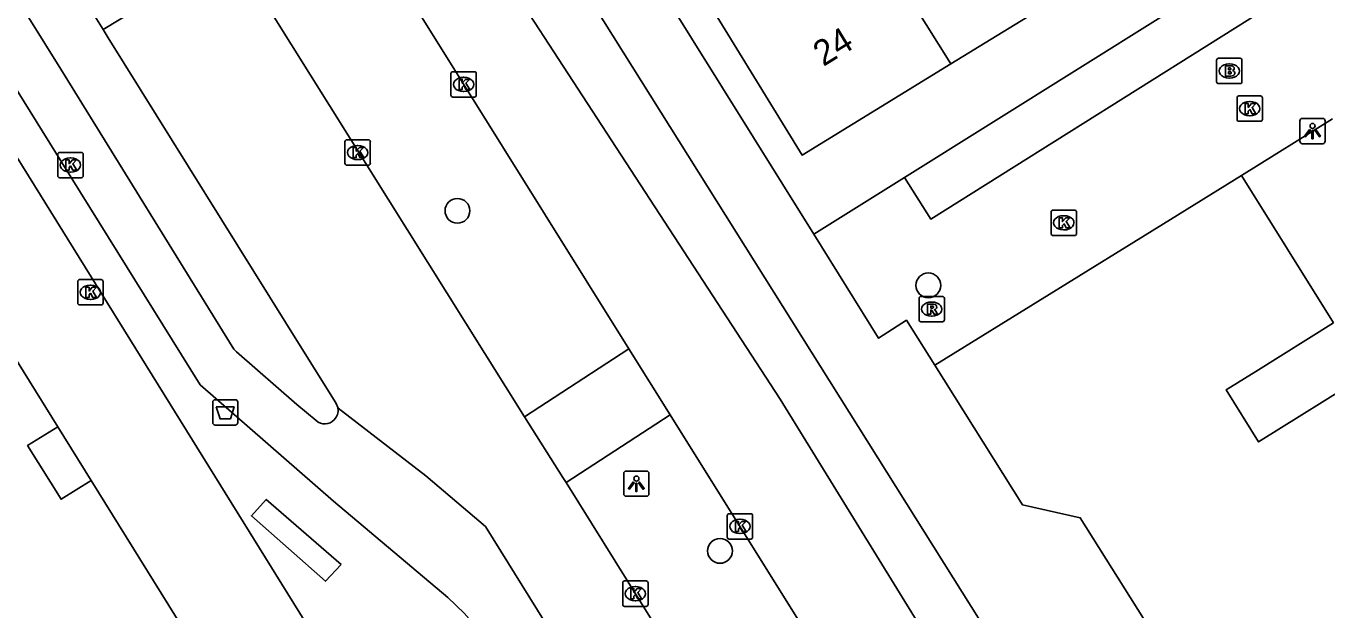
# Model space of a CAD drawing. Extents: x 158461 to 159795, y 387220 to 388672.
# Drawn here: x 158762.6 to 158813.9, y 388009.1 to 388032.1 of the extents above; entities that cross this region are included whole.
import ezdxf

# ---------------------------------------------------------------- set-up
doc = ezdxf.new("R2010")
doc.units = 0
for name, color, linetype in [('IMGEO_Afvalbak', 7, 'Continuous'), ('IMGEO_Boom', 7, 'Continuous'), ('IMGEO_Brandkraan', 7, 'Continuous'), ('IMGEO_Kolk', 7, 'Continuous'), ('IMGEO_Lichtpunt', 7, 'Continuous'), ('IMGEO_Muur', 7, 'Continuous'), ('IMGEO_Pand', 7, 'Continuous'), ('IMGEO_Pand_nummerreeks', 7, 'Continuous'), ('IMGEO_Pand_overbouw', 7, 'Continuous'), ('IMGEO_Parkeervlak_open', 7, 'Continuous'), ('IMGEO_Rijbaan_lokaal_gesloten', 7, 'Continuous'), ('IMGEO_Rijbaan_lokaal_open', 7, 'Continuous'), ('IMGEO_Rioolput', 7, 'Continuous'), ('IMGEO_Voetpad_open', 7, 'Continuous')]:
    doc.layers.add(name, color=color, linetype=linetype)

msp = doc.modelspace()

# ---------------------------------------------------------------- linework, layer by layer
at = {"layer": 'IMGEO_Afvalbak'}
for p, q in [((158769.925, 388016.491), (158769.925, 388017.291)), ((158769.925, 388017.291), (158769.925, 388016.491)), ((158770.025, 388017.391), (158770.815, 388017.391)), ((158770.815, 388017.391), (158770.025, 388017.391)), ((158770.915, 388017.291), (158770.915, 388016.491)), ((158770.915, 388016.491), (158770.915, 388017.291)), ((158770.815, 388016.391), (158770.025, 388016.391)), ((158770.025, 388016.391), (158770.815, 388016.391))]:
    msp.add_line(p, q, dxfattribs=at)
msp.add_lwpolyline([(158770.068, 388017.105), (158770.772, 388017.105), (158770.623, 388016.635), (158770.217, 388016.635), (158770.068, 388017.105)], dxfattribs=at)
for centre, start, end in [((158770.025, 388017.291), 90, 180), ((158770.025, 388017.291), 90, 180), ((158770.815, 388017.291), 0, 90), ((158770.815, 388017.291), 360, 90), ((158770.025, 388016.491), 180, 270), ((158770.025, 388016.491), 180, 270), ((158770.815, 388016.491), 270, 0), ((158770.815, 388016.491), 270, 0)]:
    msp.add_arc(centre, 0.1, start, end, dxfattribs=at)
at = {"layer": 'IMGEO_Boom'}
for centre in [(158779.58, 388024.844), (158798.158, 388021.903), (158789.94, 388011.426)]:
    msp.add_circle(centre, 0.489, dxfattribs=at)
at = {"layer": 'IMGEO_Brandkraan'}
for p, q in [((158809.53, 388029.937), (158809.53, 388030.789)), ((158809.605, 388030.863), (158810.457, 388030.863)), ((158810.531, 388030.789), (158810.531, 388029.937)), ((158810.018, 388030.643), (158810.043, 388030.643)), ((158810.457, 388029.863), (158809.605, 388029.863)), ((158810.041, 388030.083), (158810.016, 388030.083))]:
    msp.add_line(p, q, dxfattribs=at)
for points in [[(158809.53, 388029.937), (158809.53, 388030.789)], [(158809.605, 388030.863), (158810.457, 388030.863)], [(158810.531, 388030.789), (158810.531, 388029.937)], [(158809.878, 388030.563), (158809.878, 388030.163), (158810.091, 388030.163)], [(158810.109, 388030.563), (158809.878, 388030.563)], [(158810.057, 388030.482), (158810.003, 388030.482), (158810.003, 388030.406)], [(158810.003, 388030.406), (158810.056, 388030.406)], [(158810.065, 388030.33), (158810.003, 388030.33), (158810.003, 388030.249)], [(158810.003, 388030.249), (158810.065, 388030.249)], [(158810.457, 388029.863), (158809.605, 388029.863)]]:
    msp.add_lwpolyline(points, dxfattribs=at)
for centre, radius, start, end in [((158809.607, 388030.787), 0.0765, 91.552, 178.448), ((158809.607, 388030.787), 0.0765, 91.552, 178.448), ((158810.455, 388030.787), 0.0765, 1.552, 88.448), ((158810.455, 388030.787), 0.0765, 1.552, 88.448), ((158810.058, 388030.444), 0.0379, 267.8285, 90.9355), ((158810.066, 388030.289), 0.0404, 269.8759, 90.5077), ((158810.113, 388030.418), 0.145, 59.4692, 91.5367), ((158810.138, 388030.465), 0.0922, 285.5137, 58.1501), ((158810.143, 388030.273), 0.105, 301.3115, 78.989), ((158809.607, 388029.939), 0.0765, 181.552, 268.448), ((158809.607, 388029.939), 0.0765, 181.552, 268.448), ((158810.097, 388030.414), 0.251, 268.6676, 293.5347), ((158810.455, 388029.939), 0.0765, 271.552, 358.448), ((158810.455, 388029.939), 0.0765, 271.552, 358.448)]:
    msp.add_arc(centre, radius, start, end, dxfattribs=at)
for centre, major_axis, ratio, start_param, end_param in [((158810.017, 388030.363), (-0.387, 0.002), 0.722429, 4.712389, 7.853982), ((158810.042, 388030.363), (-0.39, 0.002), 0.717154, 1.570796, 4.712389)]:
    msp.add_ellipse(centre, major_axis=major_axis, ratio=ratio, start_param=start_param, end_param=end_param, dxfattribs=at)
at = {"layer": 'IMGEO_Kolk'}
for p, q in [((158779.324, 388029.405), (158779.324, 388030.257)), ((158779.399, 388030.331), (158780.251, 388030.331)), ((158780.325, 388030.257), (158780.325, 388029.405)), ((158779.812, 388030.111), (158779.837, 388030.111)), ((158780.251, 388029.331), (158779.399, 388029.331)), ((158779.835, 388029.551), (158779.81, 388029.551)), ((158810.337, 388028.45), (158810.337, 388029.302)), ((158810.412, 388029.376), (158811.264, 388029.376)), ((158811.338, 388029.302), (158811.338, 388028.45)), ((158810.825, 388029.156), (158810.85, 388029.156)), ((158811.264, 388028.376), (158810.412, 388028.376)), ((158810.848, 388028.596), (158810.823, 388028.596)), ((158775.143, 388026.718), (158775.143, 388027.57)), ((158775.218, 388027.644), (158776.07, 388027.644)), ((158775.631, 388027.424), (158775.656, 388027.424)), ((158776.144, 388027.57), (158776.144, 388026.718)), ((158763.814, 388026.223), (158763.814, 388027.075)), ((158763.889, 388027.149), (158764.741, 388027.149)), ((158764.302, 388026.929), (158764.327, 388026.929)), ((158764.815, 388027.075), (158764.815, 388026.223)), ((158776.07, 388026.644), (158775.218, 388026.644)), ((158775.654, 388026.864), (158775.629, 388026.864)), ((158764.741, 388026.149), (158763.889, 388026.149)), ((158764.325, 388026.369), (158764.3, 388026.369)), ((158803.002, 388023.944), (158803.002, 388024.796)), ((158803.077, 388024.87), (158803.929, 388024.87)), ((158803.49, 388024.65), (158803.515, 388024.65)), ((158804.003, 388024.796), (158804.003, 388023.944)), ((158803.513, 388024.09), (158803.488, 388024.09)), ((158803.929, 388023.87), (158803.077, 388023.87)), ((158764.602, 388021.202), (158764.602, 388022.054)), ((158764.677, 388022.128), (158765.529, 388022.128)), ((158765.603, 388022.054), (158765.603, 388021.202)), ((158765.09, 388021.908), (158765.115, 388021.908)), ((158765.529, 388021.128), (158764.677, 388021.128)), ((158765.113, 388021.348), (158765.088, 388021.348)), ((158790.223, 388011.965), (158790.223, 388012.817)), ((158790.298, 388012.891), (158791.15, 388012.891)), ((158791.224, 388012.817), (158791.224, 388011.965)), ((158790.711, 388012.671), (158790.736, 388012.671)), ((158791.15, 388011.891), (158790.298, 388011.891)), ((158790.734, 388012.111), (158790.709, 388012.111)), ((158786.176, 388010.237), (158787.028, 388010.237)), ((158786.101, 388009.311), (158786.101, 388010.163)), ((158786.589, 388010.017), (158786.614, 388010.017)), ((158787.102, 388010.163), (158787.102, 388009.311)), ((158787.028, 388009.237), (158786.176, 388009.237)), ((158786.612, 388009.457), (158786.587, 388009.457))]:
    msp.add_line(p, q, dxfattribs=at)
for points in [[(158779.324, 388029.405), (158779.324, 388030.257)], [(158779.399, 388030.331), (158780.251, 388030.331)], [(158780.325, 388030.257), (158780.325, 388029.405)], [(158779.645, 388030.031), (158779.768, 388030.031), (158779.768, 388029.88), (158779.898, 388030.031), (158780.062, 388030.031), (158779.916, 388029.88), (158780.069, 388029.631), (158779.917, 388029.631), (158779.832, 388029.795), (158779.768, 388029.728), (158779.768, 388029.631), (158779.645, 388029.631), (158779.645, 388030.031)], [(158780.251, 388029.331), (158779.399, 388029.331)], [(158810.337, 388028.45), (158810.337, 388029.302)], [(158810.412, 388029.376), (158811.264, 388029.376)], [(158811.338, 388029.302), (158811.338, 388028.45)], [(158810.658, 388029.076), (158810.781, 388029.076), (158810.781, 388028.925), (158810.911, 388029.076), (158811.075, 388029.076), (158810.929, 388028.925), (158811.082, 388028.676), (158810.93, 388028.676), (158810.845, 388028.84), (158810.781, 388028.773), (158810.781, 388028.676), (158810.658, 388028.676), (158810.658, 388029.076)], [(158811.264, 388028.376), (158810.412, 388028.376)], [(158775.143, 388026.718), (158775.143, 388027.57)], [(158775.218, 388027.644), (158776.07, 388027.644)], [(158775.464, 388027.344), (158775.587, 388027.344), (158775.587, 388027.193), (158775.717, 388027.344), (158775.881, 388027.344), (158775.735, 388027.193), (158775.888, 388026.944), (158775.736, 388026.944), (158775.651, 388027.108), (158775.587, 388027.041), (158775.587, 388026.944), (158775.464, 388026.944), (158775.464, 388027.344)], [(158776.144, 388027.57), (158776.144, 388026.718)], [(158763.814, 388026.223), (158763.814, 388027.075)], [(158763.889, 388027.149), (158764.741, 388027.149)], [(158764.135, 388026.849), (158764.258, 388026.849), (158764.258, 388026.698), (158764.388, 388026.849), (158764.552, 388026.849), (158764.406, 388026.698), (158764.559, 388026.449), (158764.407, 388026.449), (158764.322, 388026.613), (158764.258, 388026.546), (158764.258, 388026.449), (158764.135, 388026.449), (158764.135, 388026.849)], [(158764.815, 388027.075), (158764.815, 388026.223)], [(158776.07, 388026.644), (158775.218, 388026.644)], [(158764.741, 388026.149), (158763.889, 388026.149)], [(158803.002, 388023.944), (158803.002, 388024.796)], [(158803.077, 388024.87), (158803.929, 388024.87)], [(158804.003, 388024.796), (158804.003, 388023.944)], [(158803.323, 388024.57), (158803.446, 388024.57), (158803.446, 388024.419), (158803.576, 388024.57), (158803.74, 388024.57), (158803.594, 388024.419), (158803.747, 388024.17), (158803.595, 388024.17), (158803.51, 388024.334), (158803.446, 388024.267), (158803.446, 388024.17), (158803.323, 388024.17), (158803.323, 388024.57)], [(158803.929, 388023.87), (158803.077, 388023.87)], [(158764.602, 388021.202), (158764.602, 388022.054)], [(158764.677, 388022.128), (158765.529, 388022.128)], [(158765.603, 388022.054), (158765.603, 388021.202)], [(158764.923, 388021.828), (158765.046, 388021.828), (158765.046, 388021.677), (158765.176, 388021.828), (158765.34, 388021.828), (158765.194, 388021.677), (158765.347, 388021.428), (158765.195, 388021.428), (158765.11, 388021.592), (158765.046, 388021.525), (158765.046, 388021.428), (158764.923, 388021.428), (158764.923, 388021.828)], [(158765.529, 388021.128), (158764.677, 388021.128)], [(158790.223, 388011.965), (158790.223, 388012.817)], [(158790.298, 388012.891), (158791.15, 388012.891)], [(158791.224, 388012.817), (158791.224, 388011.965)], [(158790.544, 388012.591), (158790.667, 388012.591), (158790.667, 388012.44), (158790.797, 388012.591), (158790.961, 388012.591), (158790.815, 388012.44), (158790.968, 388012.191), (158790.816, 388012.191), (158790.731, 388012.355), (158790.667, 388012.288), (158790.667, 388012.191), (158790.544, 388012.191), (158790.544, 388012.591)], [(158791.15, 388011.891), (158790.298, 388011.891)], [(158786.176, 388010.237), (158787.028, 388010.237)], [(158786.101, 388009.311), (158786.101, 388010.163)], [(158786.422, 388009.937), (158786.545, 388009.937), (158786.545, 388009.786), (158786.675, 388009.937), (158786.839, 388009.937), (158786.693, 388009.786), (158786.846, 388009.537), (158786.694, 388009.537), (158786.609, 388009.701), (158786.545, 388009.634), (158786.545, 388009.537), (158786.422, 388009.537), (158786.422, 388009.937)], [(158787.102, 388010.163), (158787.102, 388009.311)], [(158787.028, 388009.237), (158786.176, 388009.237)]]:
    msp.add_lwpolyline(points, dxfattribs=at)
for centre, start, end in [((158779.401, 388030.255), 91.552, 178.448), ((158779.401, 388030.255), 91.552, 178.448), ((158780.249, 388030.255), 1.552, 88.448), ((158780.249, 388030.255), 1.552, 88.448), ((158779.401, 388029.407), 181.552, 268.448), ((158779.401, 388029.407), 181.552, 268.448), ((158780.249, 388029.407), 271.552, 358.448), ((158780.249, 388029.407), 271.552, 358.448), ((158810.414, 388029.3), 91.552, 178.448), ((158810.414, 388029.3), 91.552, 178.448), ((158811.262, 388029.3), 1.552, 88.448), ((158811.262, 388029.3), 1.552, 88.448), ((158810.414, 388028.452), 181.552, 268.448), ((158810.414, 388028.452), 181.552, 268.448), ((158811.262, 388028.452), 271.552, 358.448), ((158811.262, 388028.452), 271.552, 358.448), ((158775.22, 388027.568), 91.552, 178.448), ((158775.22, 388027.568), 91.552, 178.448), ((158776.068, 388027.568), 1.552, 88.448), ((158776.068, 388027.568), 1.552, 88.448), ((158763.891, 388027.073), 91.552, 178.448), ((158763.891, 388027.073), 91.552, 178.448), ((158764.739, 388027.073), 1.552, 88.448), ((158764.739, 388027.073), 1.552, 88.448), ((158775.22, 388026.72), 181.552, 268.448), ((158775.22, 388026.72), 181.552, 268.448), ((158776.068, 388026.72), 271.552, 358.448), ((158776.068, 388026.72), 271.552, 358.448), ((158763.891, 388026.225), 181.552, 268.448), ((158763.891, 388026.225), 181.552, 268.448), ((158764.739, 388026.225), 271.552, 358.448), ((158764.739, 388026.225), 271.552, 358.448), ((158803.079, 388024.794), 91.552, 178.448), ((158803.079, 388024.794), 91.552, 178.448), ((158803.927, 388024.794), 1.552, 88.448), ((158803.927, 388024.794), 1.552, 88.448), ((158803.079, 388023.946), 181.552, 268.448), ((158803.079, 388023.946), 181.552, 268.448), ((158803.927, 388023.946), 271.552, 358.448), ((158803.927, 388023.946), 271.552, 358.448), ((158764.679, 388022.052), 91.552, 178.448), ((158764.679, 388022.052), 91.552, 178.448), ((158765.527, 388022.052), 1.552, 88.448), ((158765.527, 388022.052), 1.552, 88.448), ((158764.679, 388021.204), 181.552, 268.448), ((158764.679, 388021.204), 181.552, 268.448), ((158765.527, 388021.204), 271.552, 358.448), ((158765.527, 388021.204), 271.552, 358.448), ((158790.3, 388012.815), 91.552, 178.448), ((158790.3, 388012.815), 91.552, 178.448), ((158791.148, 388012.815), 1.552, 88.448), ((158791.148, 388012.815), 1.552, 88.448), ((158790.3, 388011.967), 181.552, 268.448), ((158790.3, 388011.967), 181.552, 268.448), ((158791.148, 388011.967), 271.552, 358.448), ((158791.148, 388011.967), 271.552, 358.448), ((158786.178, 388010.161), 91.552, 178.448), ((158786.178, 388010.161), 91.552, 178.448), ((158787.026, 388010.161), 1.552, 88.448), ((158787.026, 388010.161), 1.552, 88.448), ((158786.178, 388009.313), 181.552, 268.448), ((158786.178, 388009.313), 181.552, 268.448), ((158787.026, 388009.313), 271.552, 358.448), ((158787.026, 388009.313), 271.552, 358.448)]:
    msp.add_arc(centre, 0.0765, start, end, dxfattribs=at)
for centre, major_axis, ratio, start_param, end_param in [((158779.811, 388029.831), (-0.387, 0.002), 0.722429, 4.712389, 7.853982), ((158779.836, 388029.831), (-0.39, 0.002), 0.717154, 1.570796, 4.712389), ((158810.824, 388028.876), (-0.387, 0.002), 0.722429, 4.712389, 7.853982), ((158810.849, 388028.876), (-0.39, 0.002), 0.717154, 1.570796, 4.712389), ((158775.63, 388027.144), (-0.387, 0.002), 0.722429, 4.712389, 7.853982), ((158775.655, 388027.144), (-0.39, 0.002), 0.717154, 1.570796, 4.712389), ((158764.301, 388026.649), (-0.387, 0.002), 0.722429, 4.712389, 7.853982), ((158764.326, 388026.649), (-0.39, 0.002), 0.717154, 1.570796, 4.712389), ((158803.489, 388024.37), (-0.387, 0.002), 0.722429, 4.712389, 7.853982), ((158803.514, 388024.37), (-0.39, 0.002), 0.717154, 1.570796, 4.712389), ((158765.089, 388021.628), (-0.387, 0.002), 0.722429, 4.712389, 7.853982), ((158765.114, 388021.628), (-0.39, 0.002), 0.717154, 1.570796, 4.712389), ((158790.71, 388012.391), (-0.387, 0.002), 0.722429, 4.712389, 7.853982), ((158790.735, 388012.391), (-0.39, 0.002), 0.717154, 1.570796, 4.712389), ((158786.588, 388009.737), (-0.387, 0.002), 0.722429, 4.712389, 7.853982), ((158786.613, 388009.737), (-0.39, 0.002), 0.717154, 1.570796, 4.712389)]:
    msp.add_ellipse(centre, major_axis=major_axis, ratio=ratio, start_param=start_param, end_param=end_param, dxfattribs=at)
at = {"layer": 'IMGEO_Lichtpunt'}
for p, q in [((158812.816, 388028.394), (158812.816, 388027.587)), ((158812.816, 388028.394), (158812.816, 388027.587)), ((158813.718, 388028.489), (158812.91, 388028.489)), ((158813.718, 388028.489), (158812.91, 388028.489)), ((158813.812, 388027.587), (158813.812, 388028.394)), ((158813.812, 388027.587), (158813.812, 388028.394)), ((158812.91, 388027.493), (158813.718, 388027.493)), ((158812.91, 388027.493), (158813.718, 388027.493)), ((158786.14, 388014.48), (158786.14, 388013.673)), ((158786.14, 388014.48), (158786.14, 388013.673)), ((158787.042, 388014.575), (158786.234, 388014.575)), ((158787.042, 388014.575), (158786.234, 388014.575)), ((158787.136, 388013.673), (158787.136, 388014.48)), ((158787.136, 388013.673), (158787.136, 388014.48)), ((158786.234, 388013.579), (158787.042, 388013.579)), ((158786.234, 388013.579), (158787.042, 388013.579))]:
    msp.add_line(p, q, dxfattribs=at)
for points in [[(158813.19, 388028.058), (158813.229, 388028.03), (158813.041, 388027.768), (158813.003, 388027.795), (158813.19, 388028.058)], [(158813.292, 388028.01), (158813.339, 388028.01), (158813.339, 388027.688), (158813.292, 388027.688), (158813.292, 388028.01)], [(158813.402, 388028.03), (158813.44, 388028.057), (158813.627, 388027.795), (158813.588, 388027.767), (158813.402, 388028.03)], [(158786.514, 388014.144), (158786.553, 388014.116), (158786.365, 388013.854), (158786.327, 388013.881), (158786.514, 388014.144)], [(158786.616, 388014.096), (158786.663, 388014.096), (158786.663, 388013.774), (158786.616, 388013.774), (158786.616, 388014.096)], [(158786.726, 388014.116), (158786.764, 388014.143), (158786.951, 388013.881), (158786.912, 388013.853), (158786.726, 388014.116)]]:
    msp.add_lwpolyline(points, dxfattribs=at)
for centre in [(158813.315, 388028.192), (158786.639, 388014.278)]:
    msp.add_circle(centre, 0.0994, dxfattribs=at)
for centre, start, end in [((158812.91, 388028.394), 90, 180), ((158812.91, 388028.394), 90, 180), ((158813.718, 388028.394), 0, 90), ((158813.718, 388028.394), 0, 90), ((158812.91, 388027.587), 180, 270), ((158812.91, 388027.587), 180, 270), ((158813.718, 388027.587), 270, 0), ((158813.718, 388027.587), 270, 360), ((158786.234, 388014.48), 90, 180), ((158786.234, 388014.48), 90, 180), ((158787.042, 388014.48), 0, 90), ((158787.042, 388014.48), 0, 90), ((158786.234, 388013.673), 180, 270), ((158786.234, 388013.673), 180, 270), ((158787.042, 388013.673), 270, 0), ((158787.042, 388013.673), 270, 360)]:
    msp.add_arc(centre, 0.0946, start, end, dxfattribs=at)
at = {"layer": 'IMGEO_Muur'}
for points in [[(158807.435, 388024.334), (158810.509, 388026.233)], [(158798.408, 388018.757), (158807.435, 388024.334)], [(158798.408, 388018.757), (158801.869, 388013.247), (158804.148, 388012.735)]]:
    msp.add_lwpolyline(points, dxfattribs=at)
at = {"layer": 'IMGEO_Pand'}
for points in [[(158799.043, 388030.646), (158793.178, 388027.046), (158788.797, 388034.184), (158794.604, 388037.749)], [(158799.043, 388030.646), (158794.604, 388037.749)], [(158804.762, 388034.157), (158799.043, 388030.646)], [(158814.097, 388028.475), (158810.509, 388026.233)], [(158810.509, 388026.233), (158814.139, 388020.423)], [(158797.52, 387962.365), (158795.624, 387965.373), (158794.654, 387964.764), (158787.923, 387975.486), (158788.935, 387976.121), (158786.995, 387979.213), (158773.954, 388000), (158765.132, 388014.2), (158763.942, 388013.46), (158762.622, 388015.583), (158763.813, 388016.323), (158758.286, 388025.218)], [(158814.139, 388020.423), (158811.078, 388018.509), (158809.906, 388017.776), (158811.188, 388015.723), (158815.405, 388018.358), (158818.319, 388013.695)]]:
    msp.add_lwpolyline(points, dxfattribs=at)
at = {"layer": 'IMGEO_Pand_overbouw'}
msp.add_lwpolyline([(158763.813, 388016.323), (158762.622, 388015.583), (158763.942, 388013.46), (158765.132, 388014.2)], close=True, dxfattribs=at)
at = {"layer": 'IMGEO_Parkeervlak_open'}
msp.add_lwpolyline([(158797.222, 388026.163), (158810.837, 388034.701)], dxfattribs=at)
at = {"layer": 'IMGEO_Rijbaan_lokaal_gesloten'}
for points in [[(158774.012, 388016.565), (158773.243, 388017.195), (158770.864, 388019.277), (158770.76, 388019.38), (158763.931, 388030.431), (158755.649, 388043.722)], [(158753.852, 388043.019), (158754.038, 388042.762), (158763.975, 388026.751), (158769.433, 388017.98), (158774.688, 388013.388), (158779.204, 388009.58), (158779.842, 388008.974), (158780.048, 388008.741)], [(158759.122, 388041.859), (158759.33, 388041.521), (158761.565, 388038.461), (158764.744, 388033.385), (158765.602, 388032.001)], [(158826.242, 387967.003), (158821.291, 387974.98), (158819.155, 387978.39), (158808.574, 387995.299), (158807.699, 387996.716), (158779.748, 388041.252)], [(158777.679, 388039.896), (158792.31, 388017.418), (158834.227, 387949.391), (158871.964, 387889.05), (158887.922, 387863.502)], [(158786.347, 388019.403), (158774.752, 388037.976)], [(158765.602, 388032.001), (158770.717, 388035.097)], [(158770.717, 388035.097), (158782.225, 388016.719)], [(158765.602, 388032.001), (158765.806, 388031.671), (158773.443, 388019.409), (158774.78, 388017.262), (158774.869, 388017.05)], [(158786.347, 388019.403), (158787.973, 388016.798)], [(158774.869, 388017.05), (158778.332, 388014.385), (158779.563, 388013.342), (158780.694, 388012.384), (158785.095, 388005.301), (158793.995, 387991.082), (158802.455, 387977.515), (158810.737, 387964.275), (158822.801, 387944.946), (158836.678, 387922.775), (158853.754, 387895.444), (158877.701, 387857.148)], [(158783.864, 388014.122), (158783.741, 388014.319), (158782.225, 388016.719)], [(158811.283, 387979.426), (158806.797, 387986.65), (158798.463, 388000), (158787.973, 388016.798)], [(158783.864, 388014.122), (158792.673, 388000), (158794.325, 387997.351)]]:
    msp.add_lwpolyline(points, dxfattribs=at)
for centre, radius, start, end in [((158774.369, 388016.969), 0.506, 313.068, 9.2257), ((158774.347, 388016.933), 0.497, 227.7256, 317.8122)]:
    msp.add_arc(centre, radius, start, end, dxfattribs=at)
at = {"layer": 'IMGEO_Rijbaan_lokaal_open'}
for points in [[(158810.837, 388034.701), (158811.868, 388033.058), (158798.256, 388024.516), (158797.222, 388026.163)], [(158793.639, 388023.916), (158797.222, 388026.163)], [(158798.408, 388018.757), (158807.435, 388024.334), (158810.509, 388026.233)], [(158793.639, 388023.916), (158796.197, 388019.813), (158797.295, 388020.528), (158798.408, 388018.757)]]:
    msp.add_lwpolyline(points, dxfattribs=at)
at = {"layer": 'IMGEO_Rioolput'}
for p, q in [((158797.792, 388020.538), (158797.792, 388021.39)), ((158797.867, 388021.464), (158798.719, 388021.464)), ((158798.28, 388021.244), (158798.305, 388021.244)), ((158798.793, 388021.39), (158798.793, 388020.538)), ((158798.303, 388020.684), (158798.278, 388020.684)), ((158798.719, 388020.464), (158797.867, 388020.464))]:
    msp.add_line(p, q, dxfattribs=at)
for points in [[(158797.792, 388020.538), (158797.792, 388021.39)], [(158797.867, 388021.464), (158798.719, 388021.464)], [(158798.381, 388021.162), (158798.129, 388021.164), (158798.129, 388020.764)], [(158798.307, 388021.083), (158798.253, 388021.083), (158798.253, 388021.002)], [(158798.253, 388021.002), (158798.305, 388021.002)], [(158798.793, 388021.39), (158798.793, 388020.538)], [(158798.129, 388020.764), (158798.253, 388020.764), (158798.253, 388020.926), (158798.264, 388020.926)], [(158798.311, 388020.897), (158798.382, 388020.764), (158798.522, 388020.764), (158798.457, 388020.89)], [(158798.719, 388020.464), (158797.867, 388020.464)]]:
    msp.add_lwpolyline(points, dxfattribs=at)
for centre, radius, start, end in [((158797.869, 388021.388), 0.0765, 91.552, 178.448), ((158797.869, 388021.388), 0.0765, 91.552, 178.448), ((158798.289, 388021.191), 0.19, 274.7715, 282.9687), ((158798.313, 388020.987), 0.0964, 77.0061, 93.1865), ((158798.327, 388021.044), 0.0378, 276.6634, 79.6772), ((158798.38, 388021.052), 0.109, 350.3612, 89.416), ((158798.378, 388021.052), 0.112, 277.5842, 350.9817), ((158798.717, 388021.388), 0.0765, 1.552, 88.448), ((158798.717, 388021.388), 0.0765, 1.552, 88.448), ((158797.869, 388020.54), 0.0765, 181.552, 268.448), ((158797.869, 388020.54), 0.0765, 181.552, 268.448), ((158798.263, 388020.873), 0.0533, 26.0293, 88.6989), ((158798.362, 388020.837), 0.108, 29.5134, 73.7905), ((158798.717, 388020.54), 0.0765, 271.552, 358.448), ((158798.717, 388020.54), 0.0765, 271.552, 358.448)]:
    msp.add_arc(centre, radius, start, end, dxfattribs=at)
for centre, major_axis, ratio, start_param, end_param in [((158798.279, 388020.964), (-0.387, 0.002), 0.722429, 4.712389, 7.853982), ((158798.304, 388020.964), (-0.39, 0.002), 0.717154, 1.570796, 4.712389)]:
    msp.add_ellipse(centre, major_axis=major_axis, ratio=ratio, start_param=start_param, end_param=end_param, dxfattribs=at)
at = {"layer": 'IMGEO_Voetpad_open'}
for points in [[(158778.006, 388048.991), (158793.639, 388023.916)], [(158751.855, 388042.396), (158752.718, 388041.901), (158753.29, 388041.304), (158790.47, 387981.392), (158792.305, 387978.478), (158793.275, 387978.973), (158854.735, 387880.753)], [(158782.225, 388016.719), (158786.347, 388019.403)], [(158798.408, 388018.757), (158801.869, 388013.247), (158804.148, 388012.735), (158812.156, 388000), (158813.957, 387997.174)], [(158787.973, 388016.798), (158783.864, 388014.122)], [(158774.99, 388010.883), (158772.037, 388013.458), (158771.456, 388012.813), (158774.379, 388010.226), (158774.99, 388010.883)]]:
    msp.add_lwpolyline(points, dxfattribs=at)

# ---------------------------------------------------------------- texts
at = {"layer": 'IMGEO_Pand_nummerreeks'}
msp.add_text('24', height=1, rotation=31.5441, dxfattribs=at).set_placement((158794.015, 388030.517))

doc.saveas('drawing.dxf')
